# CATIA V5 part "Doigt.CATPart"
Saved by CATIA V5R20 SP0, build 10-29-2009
Part number: DoigtBati
Bounding box of the stored display mesh (mm): x 0 to 22, y 60 to 68, z 56.009 to 63.991
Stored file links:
  C:\Users\Thinkmotion2\Desktop\Pack 1\Retouchés\IAO_2010_1386_abergami\abergami_catiaInitial\ObjetsInitials\Doigt.CATPart
  C:\Users\Thinkmotion2\Desktop\Pack 1\Retouchés\IAO_2010_1386_abergami\abergami_catiaInitial\ObjetsInitials\Product2.CATProduct
  C:\Users\Thinkmotion2\Desktop\Pack 1\Retouchés\IAO_2010_1386_abergami\abergami_catiaInitial\ObjetsInitials\Bati.CATPart
  C:\Users\Thinkmotion2\Desktop\Pack 1\Retouchés\IAO_2010_1386_abergami\abergami_catiaInitial\ObjetsInitials\Squelettedebase.CATPart
  C:\Users\Thinkmotion2\Desktop\Pack 1\Retouchés\IAO_2010_1386_abergami\abergami_catiaInitial\ObjetsInitials\NewExcentrique.CATPart
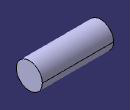
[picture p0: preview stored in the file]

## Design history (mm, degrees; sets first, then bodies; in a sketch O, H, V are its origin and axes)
External parameters (linked from other documents)
  External.DiametreDoigtBati = 8 mm
  External.LongueurDoigtBati = 12 mm
Set1
  Point1: linked copy from another document
  Plane1: linked copy from another document
Body1 (main body)
  Sketch1 on Plane1, origin (10, 0, 0), H (0, 1, 0), V (0, 0, 1)
    circle A1 centre (64, 60) radius 4
    point P1 (64, 60)
    reference projected point E1 (64, 60) from Point1
    radius A1 = 4 {= External.DiametreDoigtBati /2}
    distance P1 E1 = 0
  Pad1: profile Sketch1, direction (1, 0, 0), length 12 {= External.LongueurDoigtBati}, opposite side length 10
